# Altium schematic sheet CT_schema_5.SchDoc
size 298 x 247 mm
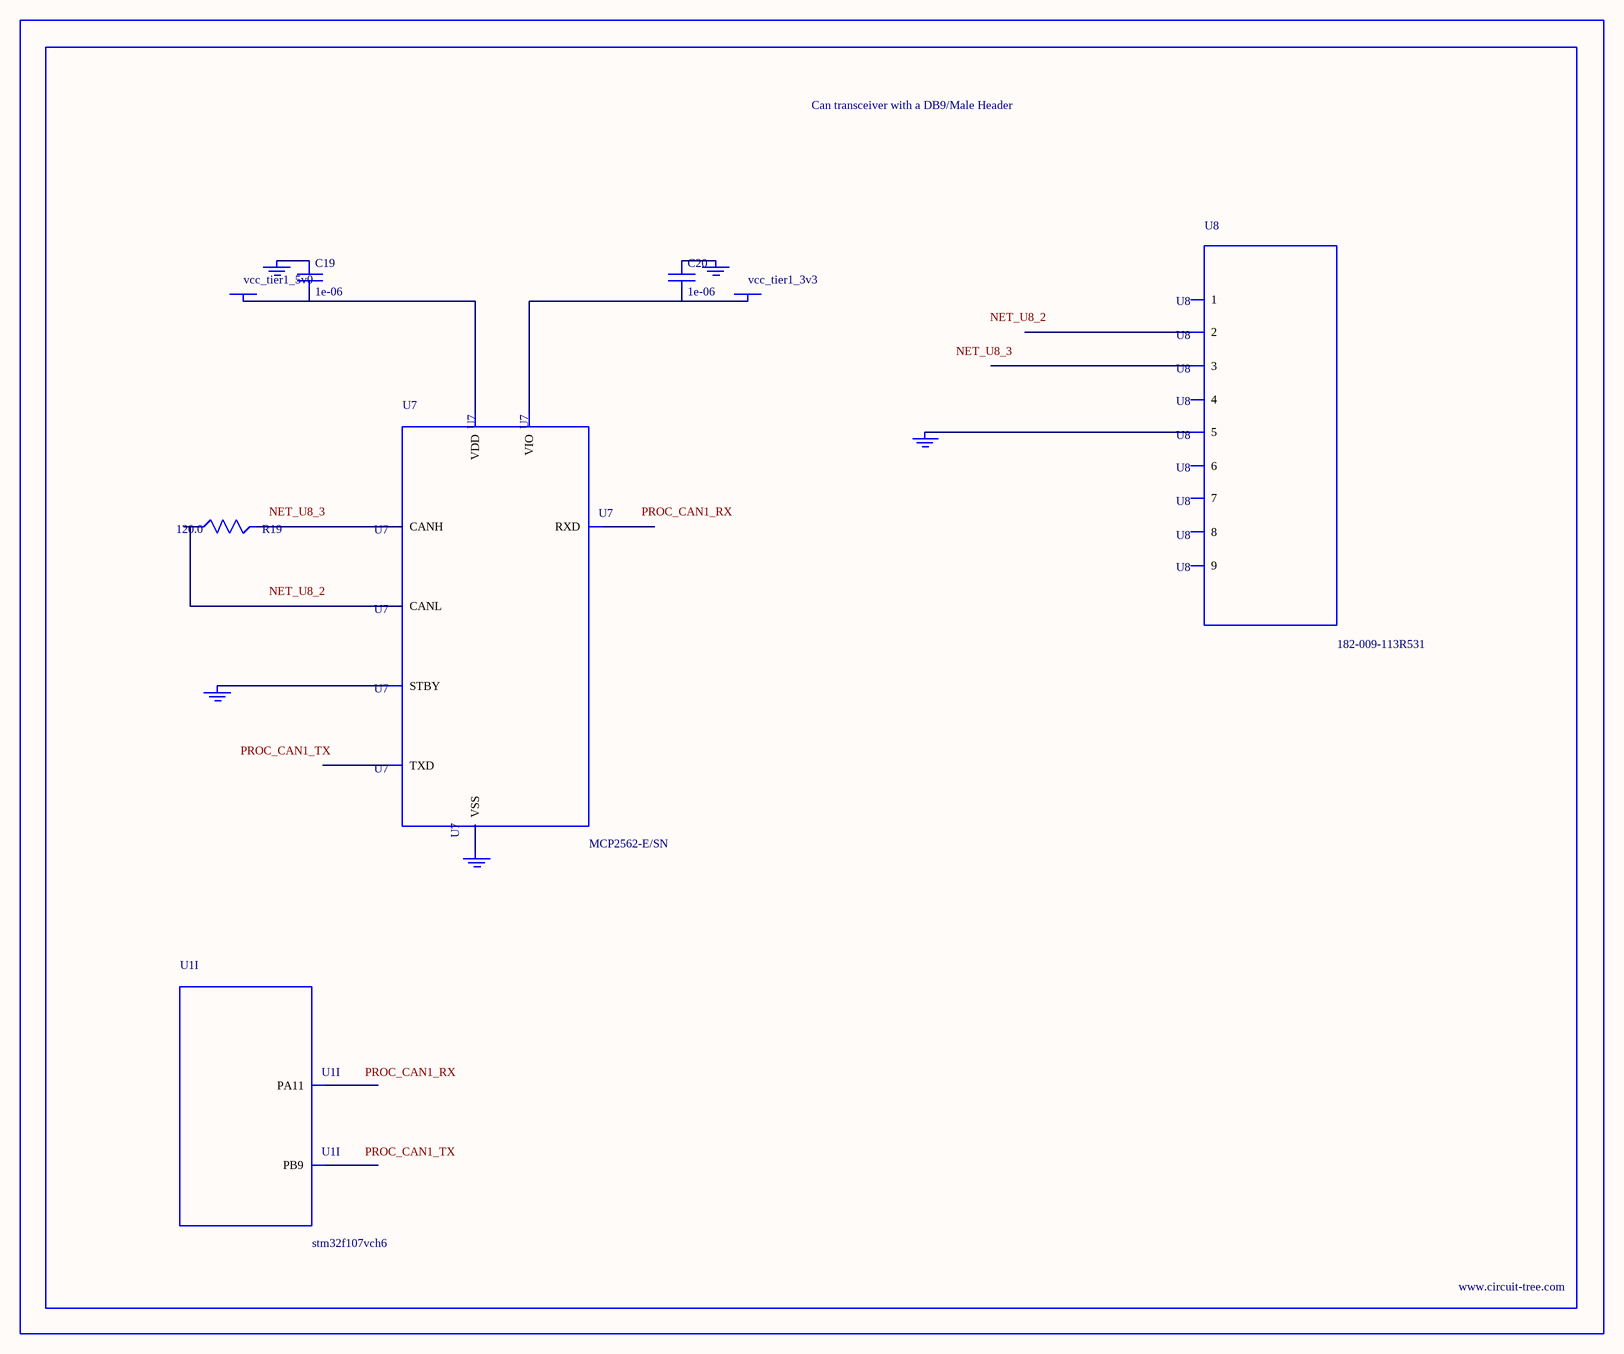
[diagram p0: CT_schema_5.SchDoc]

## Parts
BORDER4  (no value)
C19  1e-06  [C0603]
C20  1e-06  [C0603]
GND_INSTANCE_4_0  (no value)
GND_INSTANCE_4_1  (no value)
GND_INSTANCE_4_2  (no value)
GND_INSTANCE_4_3  (no value)
GND_INSTANCE_4_4  (no value)
POWER_INSTANCE_4_0  vcc_tier1_5v0
POWER_INSTANCE_4_1  vcc_tier1_3v3
R19  120.0  [R0603]
U1  stm32f107vch6  [LFBGA100]  (part I of 9)
U7  MCP2562-E/SN  [SOIC-8]
U8  182-009-113R531  [182-009-MALE]

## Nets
NetC19_1: C19.1 GND_INSTANCE_4_0.0(GND)
NetC19_2: C19.2 POWER_INSTANCE_4_0.0(PWR) U7.3(VDD)
NetC20_1: C20.1 GND_INSTANCE_4_1.0(GND)
NetC20_2: C20.2 POWER_INSTANCE_4_1.0(PWR) U7.5(VIO)
NetGND_INSTANCE_4_2_0: GND_INSTANCE_4_2.0(GND) U7.8(STBY)
NetGND_INSTANCE_4_3_0: GND_INSTANCE_4_3.0(GND) U7.2(VSS)
NetGND_INSTANCE_4_4_0: GND_INSTANCE_4_4.0(GND) U8.5
NetR19_1: R19.1 U7.6(CANL)
NetR19_2: R19.2 U7.7(CANH)

Not connected (* = marked no-connect by the designer): U1 A4(PB9) C10(PA11); U7 1(TXD) 4(RXD); U8 1 2 3 4 6 7 8 9

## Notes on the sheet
- Labels drawn without touching a wire or pin: NET_U8_2, NET_U8_3, PROC_CAN1_RX, PROC_CAN1_TX

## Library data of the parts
BORDER4 = BORDER_PAGE4
C19 C20 = C0603C105K3RACTU
GND_INSTANCE_4_0-GND_INSTANCE_4_4 = GND
POWER_INSTANCE_4_0 POWER_INSTANCE_4_1 = PWR
R19 = RC0603JR-07120RL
